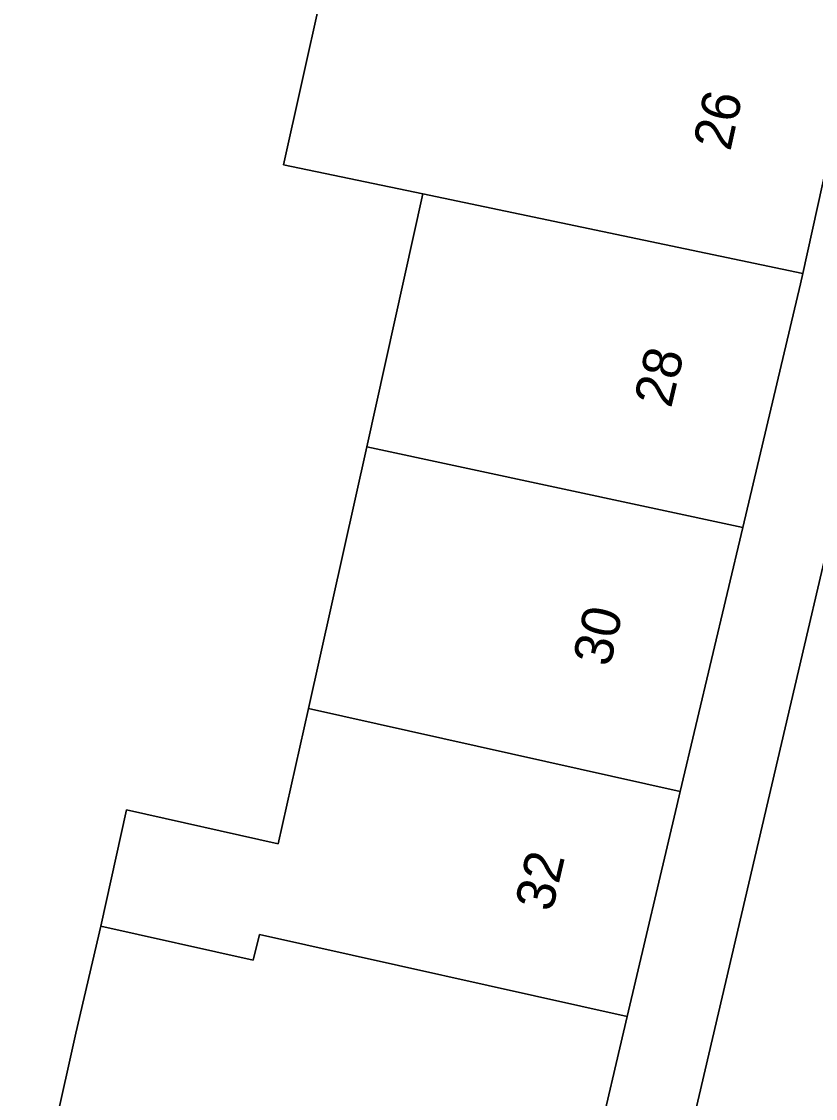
# Model space of a CAD drawing. Extents: x 161087 to 161926, y 382572 to 383873.
# Drawn here: x 161824.37 to 161844.99, y 382643.71 to 382671.69 of the extents above; entities that cross this region are included whole.
import ezdxf

# ---------------------------------------------------------------- set-up
doc = ezdxf.new("R2010")
doc.units = 0
for name, color, linetype in [('IMGEO_Erf', 7, 'Continuous'), ('IMGEO_Fietspad_gesloten', 7, 'Continuous'), ('IMGEO_Pand', 7, 'Continuous'), ('IMGEO_Pand_nummerreeks', 7, 'Continuous'), ('IMGEO_Voetpad_open', 7, 'Continuous')]:
    doc.layers.add(name, color=color, linetype=linetype)

msp = doc.modelspace()

# ---------------------------------------------------------------- linework, layer by layer
at = {"layer": 'IMGEO_Erf'}
msp.add_lwpolyline([(161824.122, 382632.789), (161831.536, 382630.953), (161836.385, 382629.733), (161836.898, 382632.179), (161832.088, 382633.286), (161829.014, 382633.97), (161828.24, 382635.188), (161823.686, 382642.442), (161828.81, 382640.736), (161828.857, 382640.949), (161828.952, 382641.375), (161825.232, 382642.956), (161825.778, 382645.409), (161826.43, 382648.19), (161827.101, 382651.206), (161831.041, 382650.329), (161831.822, 382653.84), (161833.337, 382660.644), (161834.798, 382667.21), (161831.177, 382667.968), (161832.624, 382674.469)], dxfattribs=at)
at = {"layer": 'IMGEO_Fietspad_gesloten'}
msp.add_lwpolyline([(161847.637, 382667.997), (161836.808, 382621.723)], dxfattribs=at)
at = {"layer": 'IMGEO_Pand'}
for points in [[(161834.798, 382667.21), (161844.664, 382665.145), (161846.175, 382671.975), (161836.301, 382674.064), (161836.213, 382673.67), (161832.624, 382674.469), (161831.177, 382667.968)], [(161834.798, 382667.21), (161833.337, 382660.644), (161843.104, 382658.543), (161844.603, 382664.87), (161844.664, 382665.145)], [(161843.104, 382658.543), (161833.337, 382660.644), (161831.822, 382653.84), (161841.479, 382651.69)], [(161841.479, 382651.69), (161831.822, 382653.84), (161831.041, 382650.329), (161827.101, 382651.206), (161826.43, 382648.19), (161830.387, 382647.309), (161830.554, 382647.969), (161840.106, 382645.844), (161841.391, 382651.317)], [(161840.106, 382645.844), (161830.554, 382647.969), (161830.387, 382647.309), (161826.43, 382648.19), (161825.778, 382645.409), (161825.232, 382642.956), (161828.952, 382641.375), (161828.857, 382640.949), (161838.456, 382638.814)]]:
    msp.add_lwpolyline(points, close=True, dxfattribs=at)
at = {"layer": 'IMGEO_Voetpad_open'}
for points in [[(161846.175, 382671.975), (161844.664, 382665.145), (161844.603, 382664.87), (161843.104, 382658.543), (161841.479, 382651.69), (161841.391, 382651.317), (161840.106, 382645.844), (161838.456, 382638.814), (161836.898, 382632.179), (161836.385, 382629.733), (161836.438, 382629.72), (161836.367, 382629.412), (161836.259, 382629.429), (161834.23, 382620.808)], [(161836.808, 382621.723), (161847.637, 382667.997)]]:
    msp.add_lwpolyline(points, dxfattribs=at)

# ---------------------------------------------------------------- texts
at = {"layer": 'IMGEO_Pand_nummerreeks'}
for s, rotation, p in [('26', 77.5237, (161842.781, 382668.298)), ('28', 76.7028, (161841.242, 382661.623)), ('30', 76.6671, (161839.65, 382654.898)), ('32', 76.7803, (161838.15, 382648.536))]:
    msp.add_text(s, height=1, rotation=rotation, dxfattribs=at).set_placement(p)

doc.saveas('drawing.dxf')
